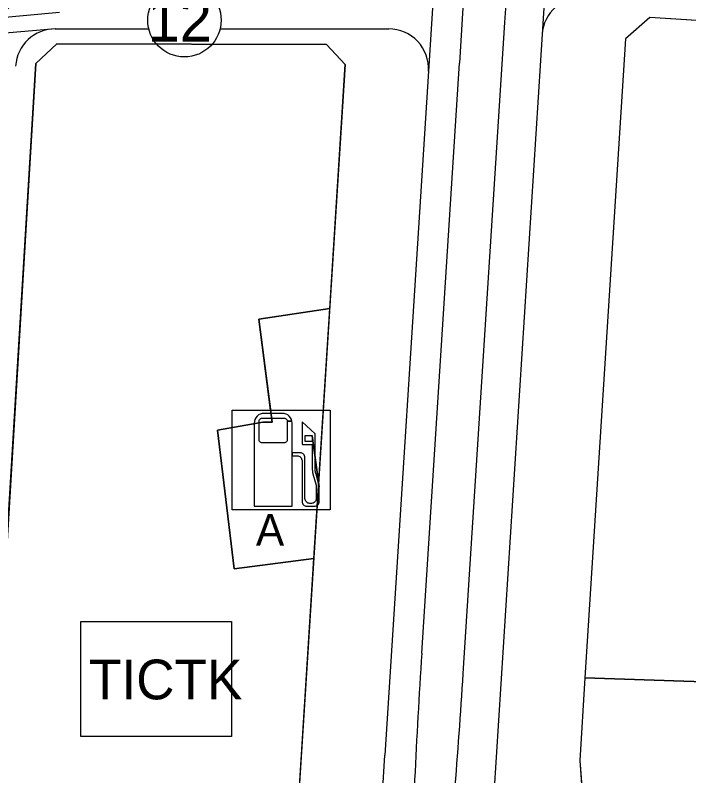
# Model space of a CAD drawing. Extents: x 419109 to 421295, y 4452223 to 4457798.
# Drawn here: x 420029.7 to 420199.2, y 4453902.7 to 4454094.1 of the extents above; entities that cross this region are included whole.
import ezdxf

# ---------------------------------------------------------------- set-up
doc = ezdxf.new("R2010")
doc.units = 0
for name, color, linetype in [('ADA', 7, 'Continuous'), ('ADAKENARI', 7, 'Continuous'), ('KALDIRIM', 7, 'Continuous'), ('KD_DAIRE', 7, 'Continuous'), ('KD_YGEN', 7, 'Continuous'), ('LJ_SEMBOL', 7, 'Continuous'), ('PL_BAKIM_AKARYAKIT', 7, 'Continuous'), ('PL_TİCT', 7, 'Continuous'), ('PL_TURZM', 7, 'Continuous'), ('RAYLI_TOPLU_TAŞIMA_HATTI', 7, 'Continuous'), ('TR_BAKIMAKARYAKIT', 7, 'Continuous'), ('TR_TİC_TURIZM_K', 7, 'Continuous'), ('TR_TİCK', 7, 'Continuous'), ('TR_TİCT', 7, 'Continuous')]:
    doc.layers.add(name, color=color, linetype=linetype)

msp = doc.modelspace()

# ---------------------------------------------------------------- linework, layer by layer
at = {"layer": 'ADA'}
for p, q in [((420108.84, 4454020.27), (420090.99, 4454017.61)), ((420090.99, 4454017.61), (420094.34, 4453991.67)), ((420092.04, 4453991.7), (420080.64, 4453989.67)), ((420094.34, 4453991.67), (420092.04, 4453991.7)), ((420080.64, 4453989.67), (420084.77, 4453954.76)), ((420084.77, 4453954.76), (420104.85, 4453957.34))]:
    msp.add_line(p, q, dxfattribs=at)
at = {"layer": 'ADAKENARI'}
for p, q in [((420189.39, 4454093.55), (420183.29, 4454088.18)), ((420262.97, 4454088.81), (420189.39, 4454093.55)), ((420183.29, 4454088.18), (420173.09, 4453927.3)), ((420034.84, 4454081.92), (420040.14, 4454086.9)), ((420040.14, 4454086.9), (420108.05, 4454086.69)), ((420108.05, 4454086.69), (420112.73, 4454081.68)), ((420024.61, 4453912.86), (420034.84, 4454081.92)), ((420112.73, 4454081.68), (420100.89, 4453894.74)), ((420173.09, 4453927.3), (420171.77, 4453906.51)), ((420267.79, 4453924.14), (420173.09, 4453927.3)), ((420171.77, 4453906.51), (420173.31, 4453886.74))]:
    msp.add_line(p, q, dxfattribs=at)
at = {"layer": 'KALDIRIM'}
for p, q in [((420163.43, 4454106.7), (420161.83, 4454081.45)), ((420135.21, 4454104), (420133.68, 4454080.03)), ((420022.57, 4454093.18), (420040.86, 4454094.89)), ((420039.89, 4454090.66), (420020.15, 4454088.98)), ((420039.77, 4454090.66), (420063.31, 4454090.66)), ((420081.24, 4454090.66), (420123.7, 4454090.66)), ((420161.91, 4454082.73), (420141.23, 4453758.24)), ((420133.68, 4454080.03), (420122.71, 4453907.91)), ((420119.93, 4453864.22), (420122.71, 4453907.91))]:
    msp.add_line(p, q, dxfattribs=at)
for centre, start, end in [((420021.09, 4454103.08), 275.3127, 356.538), ((420172.3, 4454088.63), 86.3166, 176.3547), ((420039.77, 4454080.66), 90, 176.538), ((420123.7, 4454080.66), 356.3547, 90)]:
    msp.add_arc(centre, 10, start, end, dxfattribs=at)
at = {"layer": 'KD_DAIRE'}
msp.add_circle((420072.27, 4454092.83), 9.23, dxfattribs=at)
at = {"layer": 'LJ_SEMBOL'}
for points in [[(420084.31, 4453994.7), (420108.99, 4453994.7), (420108.99, 4453969.6), (420084.31, 4453969.6)], [(420099.34, 4453991.91), (420099.2, 4453992.37), (420098.97, 4453992.8), (420098.67, 4453993.17), (420098.29, 4453993.48), (420097.87, 4453993.71), (420097.41, 4453993.85), (420096.92, 4453993.89), (420092.3, 4453993.89), (420091.82, 4453993.85), (420091.35, 4453993.71), (420090.93, 4453993.48), (420090.55, 4453993.17), (420090.25, 4453992.8), (420090.02, 4453992.37), (420089.88, 4453991.91), (420089.83, 4453991.43), (420089.83, 4453970.5), (420099.39, 4453970.5), (420099.39, 4453991.43), (420099.34, 4453991.91), (420098.16, 4453991.92), (420098.16, 4453987.24), (420098.14, 4453987.09), (420098.1, 4453986.95), (420098.03, 4453986.82), (420097.94, 4453986.71), (420097.83, 4453986.62), (420097.7, 4453986.55), (420097.56, 4453986.51), (420097.42, 4453986.5), (420091.8, 4453986.5), (420091.66, 4453986.51), (420091.52, 4453986.55), (420091.39, 4453986.62), (420091.28, 4453986.71), (420091.19, 4453986.82), (420091.12, 4453986.95), (420091.08, 4453987.09), (420091.06, 4453987.24), (420091.06, 4453991.92), (420091.08, 4453992.07), (420091.12, 4453992.2), (420091.19, 4453992.33), (420091.28, 4453992.44), (420091.39, 4453992.54), (420091.52, 4453992.6), (420091.66, 4453992.65), (420091.8, 4453992.66), (420097.42, 4453992.66), (420097.56, 4453992.65), (420097.7, 4453992.6), (420097.83, 4453992.54), (420097.94, 4453992.44), (420098.03, 4453992.33), (420098.1, 4453992.2), (420098.14, 4453992.07), (420098.16, 4453991.92)], [(420106.2, 4453975.4), (420106.2, 4453975.48), (420106.2, 4453975.56), (420106.19, 4453975.64), (420106.18, 4453975.72), (420106.17, 4453975.81), (420106.15, 4453975.89), (420106.13, 4453975.97), (420105.4, 4453978.61), (420105.3, 4453978.96), (420105.28, 4453979.05), (420105.26, 4453979.14), (420105.24, 4453979.23), (420105.22, 4453979.32), (420105.21, 4453979.41), (420105.21, 4453979.51), (420105.2, 4453979.6), (420105.2, 4453979.69), (420105.2, 4453988.61), (420105.2, 4453988.63), (420105.2, 4453988.64), (420105.19, 4453988.65), (420105.19, 4453988.66), (420105.18, 4453988.67), (420105.18, 4453988.68), (420105.17, 4453988.69), (420105.16, 4453988.7), (420101.94, 4453991.76), (420101.94, 4453986.18), (420101.94, 4453986.15), (420101.95, 4453986.13), (420101.96, 4453986.11), (420101.98, 4453986.09), (420101.99, 4453986.08), (420102.02, 4453986.06), (420102.04, 4453986.06), (420102.06, 4453986.05), (420104.34, 4453986.05), (420104.36, 4453986.05), (420104.38, 4453986.05), (420104.4, 4453986.03), (420104.42, 4453986.02), (420104.44, 4453986), (420104.45, 4453985.98), (420104.46, 4453985.96), (420104.46, 4453985.93), (420104.46, 4453979.79), (420104.46, 4453979.65), (420104.47, 4453979.5), (420104.48, 4453979.36), (420104.5, 4453979.22), (420104.52, 4453979.08), (420104.55, 4453978.94), (420104.58, 4453978.8), (420104.61, 4453978.67), (420105.41, 4453975.81), (420105.42, 4453975.76), (420105.43, 4453975.72), (420105.44, 4453975.67), (420105.45, 4453975.62), (420105.46, 4453975.58), (420105.46, 4453975.53), (420105.46, 4453975.48), (420105.46, 4453975.44), (420105.46, 4453972.47), (420105.44, 4453972.23), (420105.37, 4453972), (420105.25, 4453971.79), (420105.1, 4453971.6), (420104.91, 4453971.45), (420104.7, 4453971.33), (420104.47, 4453971.26), (420104.23, 4453971.24), (420103.84, 4453971.24), (420103.6, 4453971.26), (420103.37, 4453971.33), (420103.16, 4453971.45), (420102.97, 4453971.6), (420102.82, 4453971.79), (420102.71, 4453972), (420102.64, 4453972.23), (420102.61, 4453972.47), (420102.61, 4453982.73), (420102.59, 4453982.97), (420102.52, 4453983.21), (420102.4, 4453983.42), (420102.25, 4453983.61), (420102.06, 4453983.76), (420101.85, 4453983.87), (420101.62, 4453983.94), (420101.38, 4453983.97), (420099.39, 4453983.97), (420099.39, 4453983.23), (420100.64, 4453983.23), (420100.88, 4453983.2), (420101.11, 4453983.13), (420101.32, 4453983.02), (420101.51, 4453982.87), (420101.66, 4453982.68), (420101.78, 4453982.47), (420101.85, 4453982.23), (420101.87, 4453981.99), (420101.87, 4453971.73), (420101.9, 4453971.49), (420101.97, 4453971.26), (420102.08, 4453971.05), (420102.23, 4453970.86), (420102.42, 4453970.71), (420102.63, 4453970.59), (420102.86, 4453970.52), (420103.11, 4453970.5), (420104.97, 4453970.5), (420105.21, 4453970.52), (420105.44, 4453970.59), (420105.65, 4453970.71), (420105.84, 4453970.86), (420105.99, 4453971.05), (420106.11, 4453971.26), (420106.18, 4453971.49), (420106.2, 4453971.73), (420106.2, 4453975.4), (420104.46, 4453988.22), (420104.46, 4453986.92), (420104.46, 4453986.89), (420104.45, 4453986.87), (420104.44, 4453986.85), (420104.42, 4453986.83), (420104.4, 4453986.82), (420104.38, 4453986.8), (420104.36, 4453986.8), (420104.34, 4453986.79), (420102.8, 4453986.79), (420102.78, 4453986.8), (420102.76, 4453986.8), (420102.73, 4453986.82), (420102.72, 4453986.83), (420102.7, 4453986.85), (420102.69, 4453986.87), (420102.68, 4453986.89), (420102.68, 4453986.92), (420102.68, 4453988.22), (420102.68, 4453988.25), (420102.69, 4453988.27), (420102.7, 4453988.29), (420102.72, 4453988.31), (420102.73, 4453988.33), (420102.76, 4453988.34), (420102.78, 4453988.35), (420102.8, 4453988.35), (420104.34, 4453988.35), (420104.36, 4453988.35), (420104.38, 4453988.34), (420104.4, 4453988.33), (420104.42, 4453988.31), (420104.44, 4453988.29), (420104.45, 4453988.27), (420104.46, 4453988.25), (420104.46, 4453988.22)], [(420046.23, 4453941.54), (420084.16, 4453941.54), (420084.16, 4453912.6), (420046.23, 4453912.6)]]:
    msp.add_lwpolyline(points, close=True, dxfattribs=at)
at = {"layer": 'PL_BAKIM_AKARYAKIT'}
msp.add_lwpolyline([(420104.85, 4453957.34), (420108.84, 4454020.27), (420090.99, 4454017.61), (420094.34, 4453991.67), (420092.04, 4453991.7), (420080.64, 4453989.67), (420084.77, 4453954.76), (420104.85, 4453957.34)], dxfattribs=at)
at = {"layer": 'PL_TİCT'}
msp.add_lwpolyline([(420267.79, 4453924.14), (420173.09, 4453927.3), (420171.77, 4453906.51), (420173.31, 4453886.74), (420170.86, 4453846.3), (420173.84, 4453837.54), (420177.64, 4453833.18), (420180.79, 4453830.17), (420184.21, 4453827.46), (420187.85, 4453825.08), (420191.7, 4453823.04), (420195.73, 4453821.36), (420200, 4453820.03)], dxfattribs=at)
at = {"layer": 'PL_TURZM'}
for points in [[(420264.84, 4454023.72), (420264.87, 4454031.71), (420268.28, 4454082.75), (420262.97, 4454088.81), (420189.39, 4454093.55), (420183.29, 4454088.18), (420173.09, 4453927.3)], [(420102.08, 4453879.87), (420100.89, 4453894.74), (420104.85, 4453957.34), (420084.77, 4453954.76), (420080.64, 4453989.67), (420092.04, 4453991.7), (420094.34, 4453991.67), (420090.99, 4454017.61), (420108.84, 4454020.27), (420112.73, 4454081.68), (420108.05, 4454086.69), (420040.14, 4454086.9), (420034.84, 4454081.92), (420024.61, 4453912.86)], [(420173.09, 4453927.3), (420267.79, 4453924.14), (420267.95, 4453926.85), (420268.84, 4453941.85), (420269.73, 4453956.85), (420270.11, 4453963.24), (420270.62, 4453971.85), (420271.5, 4453986.85), (420272.01, 4453995.45)]]:
    msp.add_lwpolyline(points, dxfattribs=at)
at = {"layer": 'RAYLI_TOPLU_TAŞIMA_HATTI'}
for p, q in [((420142.45, 4453928.39), (420152.91, 4454092.26)), ((420131.99, 4453933.54), (420141.47, 4454082.05))]:
    msp.add_line(p, q, dxfattribs=at)
for centre, radius, start, end in [((418156.97, 4454219.69), 2000, 356.347, 357.96847), ((425131.31, 4453763.48), 5000, 175.83533, 176.347), ((422127.93, 4453806.11), 2000, 176.347, 178.17325), ((418146.51, 4454055.82), 2000, 354.61521, 356.347)]:
    msp.add_arc(centre, radius, start, end, dxfattribs=at)
at = {"layer": 'TR_BAKIMAKARYAKIT'}
msp.add_lwpolyline([(420084.77, 4453954.76), (420104.85, 4453957.34), (420108.84, 4454020.27), (420090.99, 4454017.61), (420094.34, 4453991.67), (420092.04, 4453991.7), (420080.64, 4453989.67), (420084.77, 4453954.76)], dxfattribs=at)
at = {"layer": 'TR_TİC_TURIZM_K'}
for points in [[(420264.84, 4454023.72), (420264.87, 4454031.71), (420268.28, 4454082.75), (420262.97, 4454088.81), (420189.39, 4454093.55), (420183.29, 4454088.18)], [(420183.29, 4454088.18), (420173.09, 4453927.3), (420267.79, 4453924.14), (420267.95, 4453926.85), (420268.84, 4453941.85), (420269.73, 4453956.85), (420270.11, 4453963.24), (420270.62, 4453971.85), (420271.5, 4453986.85), (420272.01, 4453995.45)]]:
    msp.add_lwpolyline(points, dxfattribs=at)
at = {"layer": 'TR_TİCK'}
for points in [[(420084.31, 4453990.32), (420084.31, 4453994.7), (420093.95, 4453994.7), (420090.99, 4454017.61), (420108.84, 4454020.27), (420112.73, 4454081.68), (420108.05, 4454086.69), (420040.14, 4454086.9), (420034.84, 4454081.92), (420024.61, 4453912.86)], [(419979.2, 4453864.41), (420102.08, 4453879.87), (420100.89, 4453894.74), (420104.85, 4453957.34), (420084.77, 4453954.76), (420080.64, 4453989.67), (420084.31, 4453990.32)], [(420046.23, 4453912.6), (420046.23, 4453941.54), (420084.16, 4453941.54), (420084.16, 4453912.6), (420046.23, 4453912.6)]]:
    msp.add_lwpolyline(points, dxfattribs=at)
at = {"layer": 'TR_TİCT'}
msp.add_lwpolyline([(420267.79, 4453924.14), (420173.09, 4453927.3), (420171.77, 4453906.51), (420173.31, 4453886.74), (420170.86, 4453846.3), (420173.84, 4453837.54), (420177.64, 4453833.18), (420180.79, 4453830.17), (420184.21, 4453827.46), (420187.85, 4453825.08), (420191.7, 4453823.04), (420195.73, 4453821.36), (420200, 4453820.03)], dxfattribs=at)

# ---------------------------------------------------------------- texts
at = {"layer": 'KD_YGEN'}
msp.add_text('12', height=10.905, dxfattribs=at).set_placement((420062.97, 4454087.47))
at = {"layer": 'LJ_SEMBOL'}
for s, height, p in [('A', 8, (420090.26, 4453960.58)), ('TICTK', 10, (420048.25, 4453921.92))]:
    msp.add_text(s, height=height, dxfattribs=at).set_placement(p)

doc.saveas('drawing.dxf')
